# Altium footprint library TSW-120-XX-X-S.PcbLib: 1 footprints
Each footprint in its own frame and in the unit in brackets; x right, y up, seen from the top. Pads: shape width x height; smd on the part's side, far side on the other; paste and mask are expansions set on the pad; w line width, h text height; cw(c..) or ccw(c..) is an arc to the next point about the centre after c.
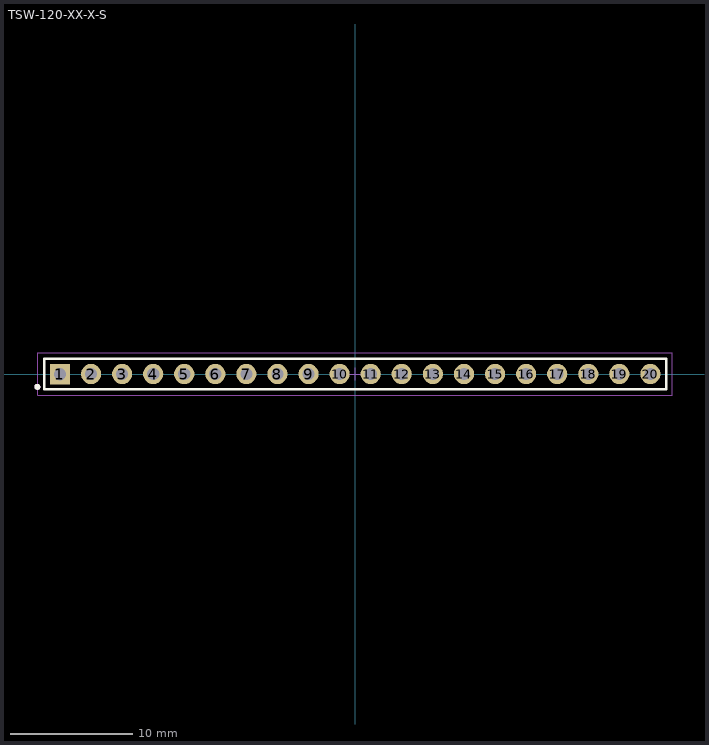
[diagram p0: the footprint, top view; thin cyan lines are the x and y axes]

## TSW-120-XX-X-S [mm] "2.54mm pitch, 20 pin, terminal strip; single row"
height 2.54
pads (20):
  rect 1.65x1.65 hole 1 mask+0: 1(-24.13,-0.025)
  round 1.65 hole 1 mask+0: 2(-21.59,0) 3(-19.05,0) 4(-16.51,0) 5(-13.97,0) 6(-11.43,0) 7(-8.89,0) 8(-6.35,0) 9(-3.81,0) 10(-1.27,0) 11(1.27,0) 12(3.81,0) 13(6.36,0) 14(8.9,0) 15(11.44,0) 16(13.98,0) 17(16.52,0) 18(19.06,0) 19(21.6,0) 20(24.14,0)
Top Overlay:
  circle w0.25: c-25.98,-1.05 r0.125
  lines w0.2: -25.43,-1.25 25.42,-1.25 25.42,1.25 -25.43,1.25 -25.43,-1.25
Mechanical 12:
  lines w0.001: -25.43,-1.25 25.42,-1.25 25.42,1.25 -25.43,1.25 -25.43,-1.25
Mechanical 13:
  circle w0.25: c-25.98,-1.05 r0.125
  lines w0.1: -25.43,-1.25 25.42,-1.25 25.42,1.25 -25.43,1.25 -25.43,-1.25
  text ".Designator" at 0,0 h1.52
Mechanical 15:
  lines w0.05: -0.5,0 0.5,0 ; 0,-0.5 0,0.5 ; -25.93,-1.75 25.92,-1.75 25.92,1.75 -25.93,1.75 -25.93,-1.75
